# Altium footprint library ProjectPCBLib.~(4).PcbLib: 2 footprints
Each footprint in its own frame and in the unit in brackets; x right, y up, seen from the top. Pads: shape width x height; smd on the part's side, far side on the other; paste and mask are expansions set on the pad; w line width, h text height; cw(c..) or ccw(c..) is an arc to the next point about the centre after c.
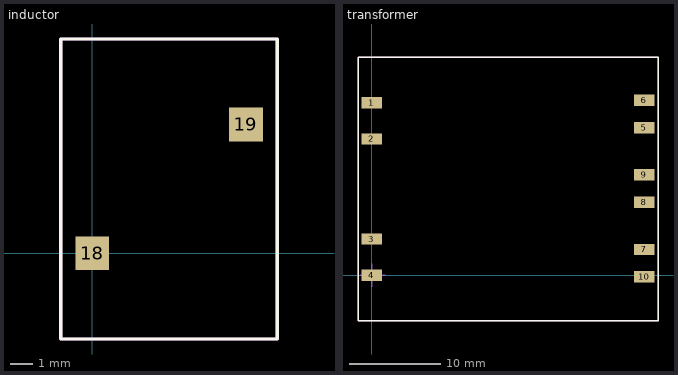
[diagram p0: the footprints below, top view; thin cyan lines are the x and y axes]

## inductor [mm]
pads (2):
  rect 1.5x1.5 smd: 18(0,0) 19(6.808,5.71)
Top Overlay:
  lines w0.15: -1.4,-3.8 -1.4,9.5 8.2,9.5 8.2,-3.8 -1.4,-3.8
Top Assembly:
  lines w0.15: -1.4,-3.8 -1.4,9.5 8.2,9.5 8.2,-3.8 -1.4,-3.8
Top Component Center:
  lines w0.15: -0.5,0 0.5,0 ; 0,-0.5 0,0.5
3D body "inductor.stp": height 12.85, standoff 0.02, extent -1.078,-3.55 7.9,9.15

## transformer [mm]
pads (10):
  rect 2.25x1.25 smd: 1(0,19) 2(0,15) 3(0,4) 4(0,0) 5(30,16.25) 6(30,19.25) 7(30,2.85) 8(30,8.05) 9(30,11.05) 10(30,-0.15)
Top Overlay:
  lines w0.15: -1.5,-5 31.5,-5 31.5,24 -1.5,24 -1.5,-5
Top Assembly:
  lines w0.15: -1.5,-5 -1.5,24 31.5,24 31.5,-5 -1.5,-5
Top Component Center:
  lines w0.15: -1.25,0 1.5,0 ; 0,-1.25 0,1.25
3D body "64.stp": height 17.75, standoff 0, extent -1,-4.8 31,23.8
